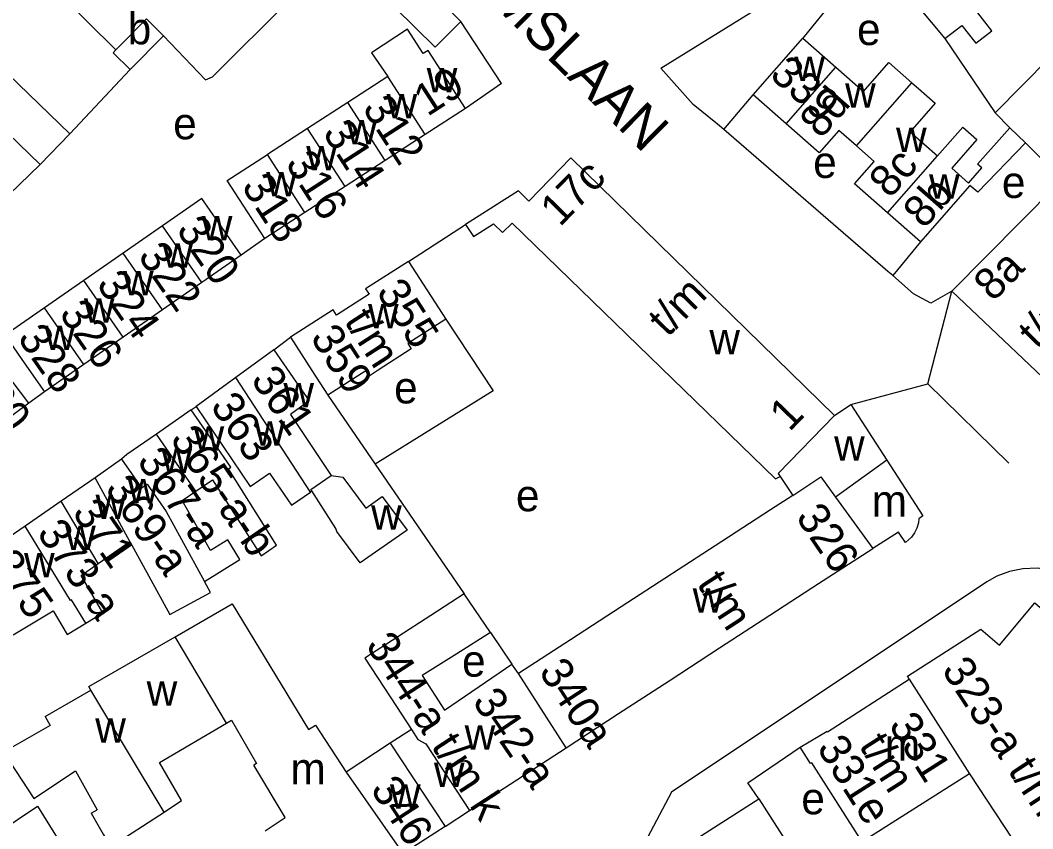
# Model space of a CAD drawing. Extents: x 159045 to 160918, y 380454 to 382516.
# Drawn here: x 160022.9 to 160150.7, y 381583.2 to 381685.3 of the extents above; entities that cross this region are included whole.
import ezdxf

# ---------------------------------------------------------------- set-up
doc = ezdxf.new("R2010")
doc.units = 0
for name, color, linetype in [('BLT_Basislijn', 7, 'Continuous'), ('BLT_Bebouwing', 7, 'Continuous'), ('BLT_Centroide', 7, 'Continuous'), ('BLT_Huisnummer', 7, 'Continuous'), ('BLT_Huisnummer_ tussenligend', 7, 'Continuous'), ('BLT_Huisnummer_reeks', 7, 'Continuous'), ('BLT_Onderdoorgang_en_onderverdeling', 7, 'Continuous'), ('BLT_Onderverdeling_panden', 7, 'Continuous'), ('BLT_Straatnaam', 7, 'Continuous'), ('BLT_Vlakafsluiter', 7, 'Continuous')]:
    doc.layers.add(name, color=color, linetype=linetype)

msp = doc.modelspace()

# ---------------------------------------------------------------- linework, layer by layer
at = {"layer": 'BLT_Basislijn'}
for p, q in [((160127.14, 381689.85), (160121.67, 381683.08)), ((160139.62, 381683.01), (160145.95, 381673.63)), ((160029.13, 381671), (160036.74, 381679.1)), ((160083.62, 381677.34), (160079.08, 381674.21)), ((160111.69, 381671.54), (160115.4, 381675.92)), ((160071.87, 381654.88), (160079.1, 381659.54)), ((160053.73, 381657.78), (160050.75, 381655.67)), ((160136.55, 381657.37), (160133.03, 381653.08)), ((160054.87, 381643.72), (160056.98, 381645.32)), ((160137.47, 381639.43), (160147.7, 381629.41)), ((160025.93, 381638.39), (160023.92, 381636.98)), ((160061.7, 381637.99), (160067.68, 381629.25)), ((160044.46, 381636.11), (160045.06, 381636.55)), ((160067.68, 381629.25), (160078.9, 381612.87)), ((160082.22, 381608), (160084.95, 381604))]:
    msp.add_line(p, q, dxfattribs=at)
for points in [[(160103.73, 381679.28), (160125.07, 381692.52), (160127.01, 381693.56), (160128.59, 381692.94), (160129.85, 381692.34)], [(160040.95, 381683.36), (160046.23, 381677.82), (160047.12, 381678.17), (160056.87, 381687.9)], [(160083.62, 381677.34), (160078.49, 381685.19)], [(160111.69, 381671.54), (160110.9, 381672.22), (160107.82, 381674.68), (160103.73, 381679.28)], [(160133.03, 381653.08), (160132.43, 381653.59), (160111.69, 381671.54)], [(160025.39, 381667.13), (160021.42, 381663.29), (160019.84, 381663.66), (160011.18, 381654.32), (160011.08, 381653.33), (160018.61, 381644.05)], [(160140.48, 381651.11), (160137.86, 381649.61), (160135.67, 381650.78), (160133.03, 381653.08)], [(160076.59, 381647.58), (160082.57, 381638.53), (160067.68, 381629.25)], [(160157.41, 381613.8), (160156.17, 381614.66), (160154.62, 381615.42), (160153.06, 381615.89), (160151.26, 381616.13), (160149.47, 381616.06), (160147.8, 381615.72), (160146.17, 381615.11), (160144.91, 381614.4), (160105.09, 381587.84), (160101.3, 381580.69)], [(160116.12, 381586.99), (160114.75, 381589), (160121.35, 381593.53)], [(160014.97, 381579.35), (160025.04, 381586.09), (160028.83, 381579.95)]]:
    msp.add_lwpolyline(points, dxfattribs=at)
at = {"layer": 'BLT_Bebouwing'}
for p, q in [((160068.34, 381695.18), (160078.49, 381685.19)), ((160040.95, 381683.36), (160038.79, 381685.5)), ((160036.74, 381679.1), (160040.95, 381683.36)), ((160115.4, 381675.92), (160121.67, 381683.08)), ((160121.67, 381683.08), (160125.84, 381679.43)), ((160152.83, 381680.58), (160145.95, 381673.63)), ((160069.28, 381678.23), (160064.21, 381674.95)), ((160119.57, 381672.27), (160115.4, 381675.92)), ((160064.21, 381674.95), (160059.14, 381671.66)), ((160079.08, 381674.21), (160074.01, 381670.92)), ((160145.95, 381673.63), (160147.84, 381671.76)), ((160025.39, 381667.13), (160029.13, 381671)), ((160059.14, 381671.66), (160054.07, 381668.38)), ((160074.01, 381670.92), (160068.94, 381667.64)), ((160068.94, 381667.64), (160063.87, 381664.35)), ((160140.48, 381651.11), (160154.45, 381665.22)), ((160063.87, 381664.35), (160058.8, 381661.07)), ((160058.8, 381661.07), (160053.73, 381657.78)), ((160136.55, 381657.37), (160132.39, 381661.01)), ((160040.8, 381659.38), (160035.84, 381655.92)), ((160035.84, 381655.92), (160030.87, 381652.47)), ((160050.75, 381655.67), (160045.79, 381652.21)), ((160071.87, 381654.88), (160076.59, 381647.58)), ((160030.87, 381652.47), (160025.91, 381649.01)), ((160045.79, 381652.21), (160040.82, 381648.76)), ((160040.82, 381648.76), (160035.86, 381645.3)), ((160035.86, 381645.3), (160030.89, 381641.85)), ((160054.87, 381643.72), (160050.06, 381640.21)), ((160030.89, 381641.85), (160025.93, 381638.39)), ((160050.06, 381640.21), (160045.06, 381636.55)), ((160023.92, 381636.98), (160019.71, 381633.82)), ((160125.69, 381635.42), (160127.76, 381636.8)), ((160044.46, 381636.11), (160040.06, 381633.07)), ((160035.66, 381629.88), (160032.31, 381627.56)), ((160032.31, 381627.56), (160028.01, 381624.59)), ((160059.69, 381625.88), (160059.5, 381625.75)), ((160120.4, 381625.31), (160117.61, 381623.5)), ((160028.01, 381624.59), (160023.46, 381621.45)), ((160117.61, 381623.5), (160111.46, 381619.51)), ((160023.46, 381621.45), (160017.51, 381617.34)), ((160032.69, 381616.71), (160036.7, 381619.48)), ((160111.46, 381619.51), (160105.09, 381615.37)), ((160123.66, 381614.21), (160130.52, 381618.6)), ((160105.09, 381615.37), (160098.72, 381611.23)), ((160117.52, 381610.21), (160123.66, 381614.21)), ((160082.22, 381608), (160078.9, 381612.87)), ((160042.44, 381607.48), (160049.63, 381611.62)), ((160098.72, 381611.23), (160092.35, 381607.09)), ((160111.15, 381606.06), (160117.52, 381610.21)), ((160092.35, 381607.09), (160085.76, 381602.81)), ((160104.79, 381601.92), (160111.15, 381606.06)), ((160085.76, 381602.81), (160084.95, 381604)), ((160098.42, 381597.77), (160104.79, 381601.92)), ((160026, 381597.41), (160031.78, 381600.74)), ((160091.81, 381593.43), (160098.42, 381597.77)), ((160040.42, 381591.57), (160048.92, 381596.57)), ((160060.12, 381596.31), (160064, 381590.38)), ((160072.25, 381595.77), (160069.59, 381594.03)), ((160069.59, 381594.03), (160064, 381590.38)), ((160083.16, 381587.84), (160091.81, 381593.43)), ((160142.71, 381590.17), (160129.19, 381581.56)), ((160142.71, 381590.17), (160150.2, 381578.82)), ((160079.6, 381585.52), (160083.16, 381587.84)), ((160106.79, 381581.02), (160116.12, 381586.99)), ((160031.83, 381585.17), (160032.58, 381585.6)), ((160031.83, 381585.17), (160033.34, 381582.55)), ((160076.5, 381583.5), (160079.6, 381585.52))]:
    msp.add_line(p, q, dxfattribs=at)
for points in [[(160014.07, 381709.89), (160010.23, 381706), (160034.94, 381681.61)], [(160078.49, 381685.19), (160075.26, 381681.92), (160065.13, 381691.92), (160068.34, 381695.18)], [(160029.13, 381671), (160013.52, 381686.08), (160004.9, 381694.4), (160001.16, 381690.52)], [(160131.15, 381693.44), (160134.23, 381689.51), (160139.62, 381683.01)], [(160139.62, 381683.01), (160141.76, 381684.69), (160143.53, 381682.44), (160145.56, 381684), (160143.78, 381686.27)], [(160079.08, 381674.21), (160074.35, 381681.51), (160073.74, 381681.12), (160071.75, 381684.2), (160067.23, 381681.22), (160069.28, 381678.23)], [(160010.53, 381681.48), (160025.39, 381667.13)], [(160034.94, 381681.61), (160034.58, 381681.24), (160036.74, 381679.1)], [(160125.84, 381679.43), (160129.36, 381676.35), (160132.54, 381679.99), (160135.45, 381677.45)], [(160135.45, 381677.45), (160136.3, 381676.7), (160138.41, 381674.86), (160135.24, 381671.23), (160138.68, 381668.21)], [(160128.46, 381669.46), (160126.22, 381671.43), (160123.74, 381668.61), (160119.57, 381672.27)], [(160138.68, 381668.21), (160141.87, 381671.85), (160143.66, 381670.28), (160140.48, 381666.65), (160142.62, 381664.77), (160144.27, 381666.69), (160143.72, 381667.17), (160147.84, 381671.76)], [(160149.78, 381669.84), (160143.77, 381663.61), (160142.77, 381664.48), (160136.55, 381657.37)], [(160149.78, 381669.84), (160154.45, 381665.22)], [(160053.73, 381657.78), (160051.01, 381661.98), (160049, 381665.09), (160054.07, 381668.38)], [(160132.39, 381661.01), (160128.22, 381664.66), (160130.71, 381667.5), (160128.46, 381669.46)], [(160092.4, 381667.96), (160087.06, 381662.5), (160085.77, 381663.77), (160079.1, 381659.54)], [(160125.69, 381635.42), (160092.4, 381667.96)], [(160050.75, 381655.67), (160047.9, 381659.77), (160045.77, 381662.83), (160040.8, 381659.38)], [(160079.1, 381659.54), (160080.08, 381658.02), (160082.6, 381659.63), (160083.77, 381658.52), (160084.97, 381659.71), (160118.22, 381627.41), (160118.8, 381627.73)], [(160071.87, 381654.88), (160066.47, 381651.41), (160066.91, 381650.72), (160062.81, 381648.08), (160062.36, 381648.77), (160056.98, 381645.32)], [(160169.66, 381650.16), (160156.01, 381636.38), (160140.48, 381651.11)], [(160025.91, 381649.01), (160020.94, 381645.55), (160023.07, 381642.5), (160025.93, 381638.39)], [(160076.59, 381647.58), (160071.81, 381644.5), (160072.24, 381643.83), (160068.04, 381641.12), (160066.91, 381640.39), (160066.48, 381641.07), (160061.7, 381637.99)], [(160056.98, 381645.32), (160059.69, 381641.11), (160061.7, 381637.99)], [(160023.92, 381636.98), (160020.91, 381640.98), (160018.61, 381644.05)], [(160054.87, 381643.72), (160057.71, 381639.61), (160059.33, 381637.27), (160056.98, 381635.53), (160062.14, 381627.82)], [(160045.06, 381636.55), (160051.91, 381626.46), (160054.32, 381628.12), (160057.1, 381624.1), (160059.5, 381625.75)], [(160127.76, 381636.8), (160132.3, 381629.77)], [(160045.04, 381625.86), (160047.14, 381627.31), (160053.29, 381617.7), (160055.21, 381619.05), (160049.14, 381628.69), (160049.44, 381628.89), (160047.31, 381631.99), (160044.46, 381636.11)], [(160040.06, 381633.07), (160036.32, 381630.48), (160035.66, 381629.88)], [(160132.3, 381629.77), (160136.85, 381622.75), (160136.33, 381622.38), (160136.27, 381621.86), (160136.09, 381621.2), (160135.8, 381620.59), (160135.4, 381620.04), (160134.64, 381619.37), (160133.75, 381620.69), (160130.52, 381618.6)], [(160062.14, 381627.82), (160063.61, 381627.63), (160066.48, 381623.73), (160068.58, 381625.19)], [(160118.8, 381627.73), (160120.4, 381625.31)], [(160046.14, 381614.44), (160050.6, 381617.23), (160049.08, 381619.7), (160046.87, 381618.35), (160043.3, 381624.66), (160045.04, 381625.86)], [(160068.58, 381625.19), (160071.72, 381620.92), (160065.77, 381616.79), (160062.83, 381620.75), (160062.72, 381621.13), (160059.69, 381625.88)], [(160036.7, 381619.48), (160041.73, 381610.26), (160046.88, 381613.08), (160046.14, 381614.44)], [(160031.12, 381609.17), (160033.3, 381610.48), (160030.53, 381615.22), (160032.69, 381616.71)], [(160078.9, 381612.87), (160074.71, 381610.15), (160066.39, 381604.75), (160070.35, 381598.68), (160072.25, 381595.77)], [(160021.97, 381607.73), (160027.01, 381610.75), (160028.8, 381607.77), (160031.12, 381609.17)], [(160049.63, 381611.62), (160059.24, 381595.74), (160060.12, 381596.31)], [(160135.12, 381602.13), (160134.89, 381602.48), (160144.17, 381608.41), (160146.51, 381606.41), (160151, 381611.74), (160166.85, 381597.9)], [(160031.78, 381600.74), (160031.53, 381601.18), (160042.44, 381607.48)], [(160082.22, 381608), (160077.99, 381605.33), (160073.61, 381602.56), (160076.42, 381598.2)], [(160076.42, 381598.2), (160080.81, 381601.19), (160084.95, 381604)], [(160121.35, 381593.53), (160124.74, 381595.56), (160124.81, 381595.45), (160135.12, 381602.13)], [(160026, 381597.41), (160026.63, 381596.28), (160020.74, 381592.91), (160024.56, 381587.02), (160029.82, 381590.55), (160032.58, 381585.6)], [(160048.92, 381596.57), (160049.55, 381596.93), (160052.67, 381591.45), (160052.37, 381591.25)], [(160129.19, 381581.56), (160122.81, 381591.56), (160122.67, 381591.47), (160121.35, 381593.53)], [(160041.01, 381585.3), (160043.21, 381586.77), (160040.42, 381591.57)], [(160053.79, 381582.95), (160056.32, 381584.64), (160052.37, 381591.25)], [(160116.12, 381586.99), (160121.64, 381578.37), (160121.73, 381578.43)], [(160033.34, 381582.55), (160034.26, 381580.95), (160041.01, 381585.3)], [(160076.5, 381583.5), (160075.21, 381582.66), (160071.22, 381580.08)]]:
    msp.add_lwpolyline(points, dxfattribs=at)
at = {"layer": 'BLT_Onderdoorgang_en_onderverdeling'}
msp.add_line((160069.59, 381594.03), (160076.5, 381583.5), dxfattribs=at)
at = {"layer": 'BLT_Onderverdeling_panden'}
for p, q in [((160038.79, 381685.5), (160034.94, 381681.61)), ((160119.57, 381672.27), (160125.84, 381679.43)), ((160074.01, 381670.92), (160069.28, 381678.23)), ((160128.46, 381669.46), (160135.45, 381677.45)), ((160068.94, 381667.64), (160064.21, 381674.95)), ((160063.87, 381664.35), (160059.14, 381671.66)), ((160147.84, 381671.76), (160149.78, 381669.84)), ((160058.8, 381661.07), (160054.07, 381668.38)), ((160132.39, 381661.01), (160138.68, 381668.21)), ((160045.79, 381652.21), (160040.8, 381659.38)), ((160040.82, 381648.76), (160035.84, 381655.92)), ((160035.86, 381645.3), (160030.87, 381652.47)), ((160030.89, 381641.85), (160025.91, 381649.01)), ((160059.5, 381625.75), (160050.06, 381640.21)), ((160045.04, 381625.86), (160040.06, 381633.07)), ((160035.66, 381629.88), (160038.16, 381626.26)), ((160132.3, 381629.77), (160125.82, 381625.09)), ((160036.7, 381619.48), (160032.31, 381627.56)), ((160038.16, 381626.26), (160038.89, 381626.76)), ((160038.89, 381626.76), (160041.3, 381623.27)), ((160125.82, 381625.09), (160130.52, 381618.6)), ((160032.69, 381616.71), (160028.01, 381624.59)), ((160041.3, 381623.27), (160046.14, 381614.44)), ((160048.92, 381596.57), (160042.44, 381607.48)), ((160091.81, 381593.43), (160085.76, 381602.81)), ((160135.12, 381602.13), (160142.71, 381590.17)), ((160041.01, 381585.3), (160031.78, 381600.74)), ((160064, 381590.38), (160071.22, 381580.08))]:
    msp.add_line(p, q, dxfattribs=at)
for points in [[(160125.69, 381635.42), (160118.56, 381628.09), (160118.8, 381627.73)], [(160059.69, 381625.88), (160059.57, 381626.05), (160062.14, 381627.82)], [(160120.4, 381625.31), (160123.95, 381627.68), (160125.82, 381625.09)], [(160031.12, 381609.17), (160029.33, 381612.14), (160029.19, 381612.06), (160023.46, 381621.45)], [(160072.25, 381595.77), (160073.08, 381594.49), (160074.09, 381593.96), (160079.6, 381585.52)]]:
    msp.add_lwpolyline(points, dxfattribs=at)
at = {"layer": 'BLT_Vlakafsluiter'}
for p, q in [((160137.47, 381639.43), (160140.48, 381651.11)), ((160127.76, 381636.8), (160137.47, 381639.43))]:
    msp.add_line(p, q, dxfattribs=at)

# ---------------------------------------------------------------- texts
at = {"layer": 'BLT_Centroide'}
for s, p in [('b', (160036.43, 381682.3)), ('e', (160128.53, 381682.2)), ('w', (160120.61, 381677.67)), ('w', (160074.19, 381676.22)), ('w', (160127.02, 381674.31)), ('w', (160069.11, 381672.94)), ('e', (160042.17, 381670.3)), ('w', (160064.05, 381669.66)), ('w', (160133.45, 381668.69)), ('w', (160058.97, 381666.38)), ('e', (160122.99, 381665.42)), ('w', (160053.91, 381663.09)), ('w', (160137.62, 381662.8)), ('e', (160146.82, 381662.89)), ('w', (160045.78, 381657.52)), ('w', (160040.81, 381654.08)), ('w', (160035.84, 381650.61)), ('w', (160030.89, 381647.16)), ('w', (160066.77, 381646.44)), ('w', (160025.92, 381643.7)), ('w', (160109.88, 381643.16)), ('w', (160056.09, 381636.45)), ('e', (160070.07, 381636.94)), ('w', (160044.75, 381630.98)), ('w', (160052.44, 381631.61)), ('w', (160125.63, 381629.73)), ('w', (160040.69, 381628.16)), ('w', (160036.45, 381624.33)), ('e', (160085.45, 381623.32)), ('w', (160032.36, 381622.36)), ('m', (160130.38, 381622.64)), ('w', (160067.16, 381621)), ('w', (160028.53, 381618.44)), ('w', (160023.34, 381614.97)), ('w', (160107.78, 381610.5)), ('e', (160078.65, 381602.43)), ('w', (160038.82, 381598.75)), ('w', (160032.33, 381594.08)), ('w', (160078.98, 381593.2)), ('m', (160132.04, 381591.84)), ('m', (160056.98, 381588.81)), ('w', (160075.1, 381588.51)), ('w', (160069.55, 381585.74)), ('e', (160121.49, 381585.05))]:
    msp.add_text(s, height=4, dxfattribs=at).set_placement(p)
at = {"layer": 'BLT_Huisnummer'}
for s, rotation, p in [('339', 318.8078, (160117.34, 381678.22)), ('19', 32.9366, (160074.27, 381673.1)), ('8d', 48.8081, (160123.96, 381670.25)), ('312', 302.9381, (160065.97, 381674.23)), ('8c', 48.8073, (160132.7, 381662.71)), ('318', 302.9312, (160050.71, 381664.36)), ('8b', 48.8073, (160137, 381658.87)), ('320', 304.8285, (160042.46, 381658.85)), ('324', 304.8285, (160032.38, 381651.99)), ('328', 304.8343, (160022.41, 381645.2)), ('330', 306.8859, (160015.91, 381640.06)), ('361', 304.6277, (160051.88, 381639.93)), ('346', 303.0148, (160067, 381588.22))]:
    msp.add_text(s, height=4, rotation=rotation, dxfattribs=at).set_placement(p)
at = {"layer": 'BLT_Huisnummer_ tussenligend'}
for s, rotation, p in [('314', 302.9381, (160060.96, 381671.1)), ('316', 302.9381, (160056.25, 381667.24)), ('322', 304.8285, (160037.62, 381655.55)), ('326', 304.8285, (160027.67, 381648.27)), ('363', 304.6277, (160046.77, 381636.59)), ('371', 304.6111, (160029.32, 381623.15)), ('375', 304.6202, (160018.94, 381616.75))]:
    msp.add_text(s, height=4, rotation=rotation, dxfattribs=at).set_placement(p)
at = {"layer": 'BLT_Huisnummer_reeks'}
for s, rotation, p in [('17c', 45.6421, (160091.01, 381659.15)), ('8a', 45.2924, (160145.71, 381649.68)), ('355', 302.8952, (160067.74, 381651.03)), ('t/m', 45.6421, (160104.61, 381645.2)), ('t/m', 45.2924, (160151.32, 381643.63)), ('t/m', 302.7779, (160063.68, 381647.33)), ('359', 302.8169, (160059.41, 381645.26)), ('1', 45.8768, (160119.98, 381633.27)), ('365-a-b', 304.6152, (160041.69, 381632.42)), ('367-a', 304.6152, (160037.5, 381629.66)), ('369-a', 304.6111, (160033.46, 381626.16)), ('326', 304.254, (160120.7, 381622.57)), ('373-a', 304.6202, (160024.86, 381620.56)), ('t/m', 303.0131, (160108.21, 381614.16)), ('344-a t/m k', 303.0132, (160066.4, 381606.39)), ('340a', 303.0132, (160088.26, 381603.09)), ('323-a t/m g', 303.4131, (160139.13, 381603.26)), ('342-a', 304.2646, (160079.86, 381599.29)), ('331', 302.4964, (160132.44, 381596.31)), ('331e', 302.4964, (160123.37, 381593.43)), ('t/m', 302.4964, (160128.69, 381593.71))]:
    msp.add_text(s, height=4, rotation=rotation, dxfattribs=at).set_placement(p)
at = {"layer": 'BLT_Straatnaam'}
msp.add_text('BRAHMSLAAN', height=5, rotation=315.4166, dxfattribs=at).set_placement((160068.8, 381700.79))

doc.saveas('drawing.dxf')
